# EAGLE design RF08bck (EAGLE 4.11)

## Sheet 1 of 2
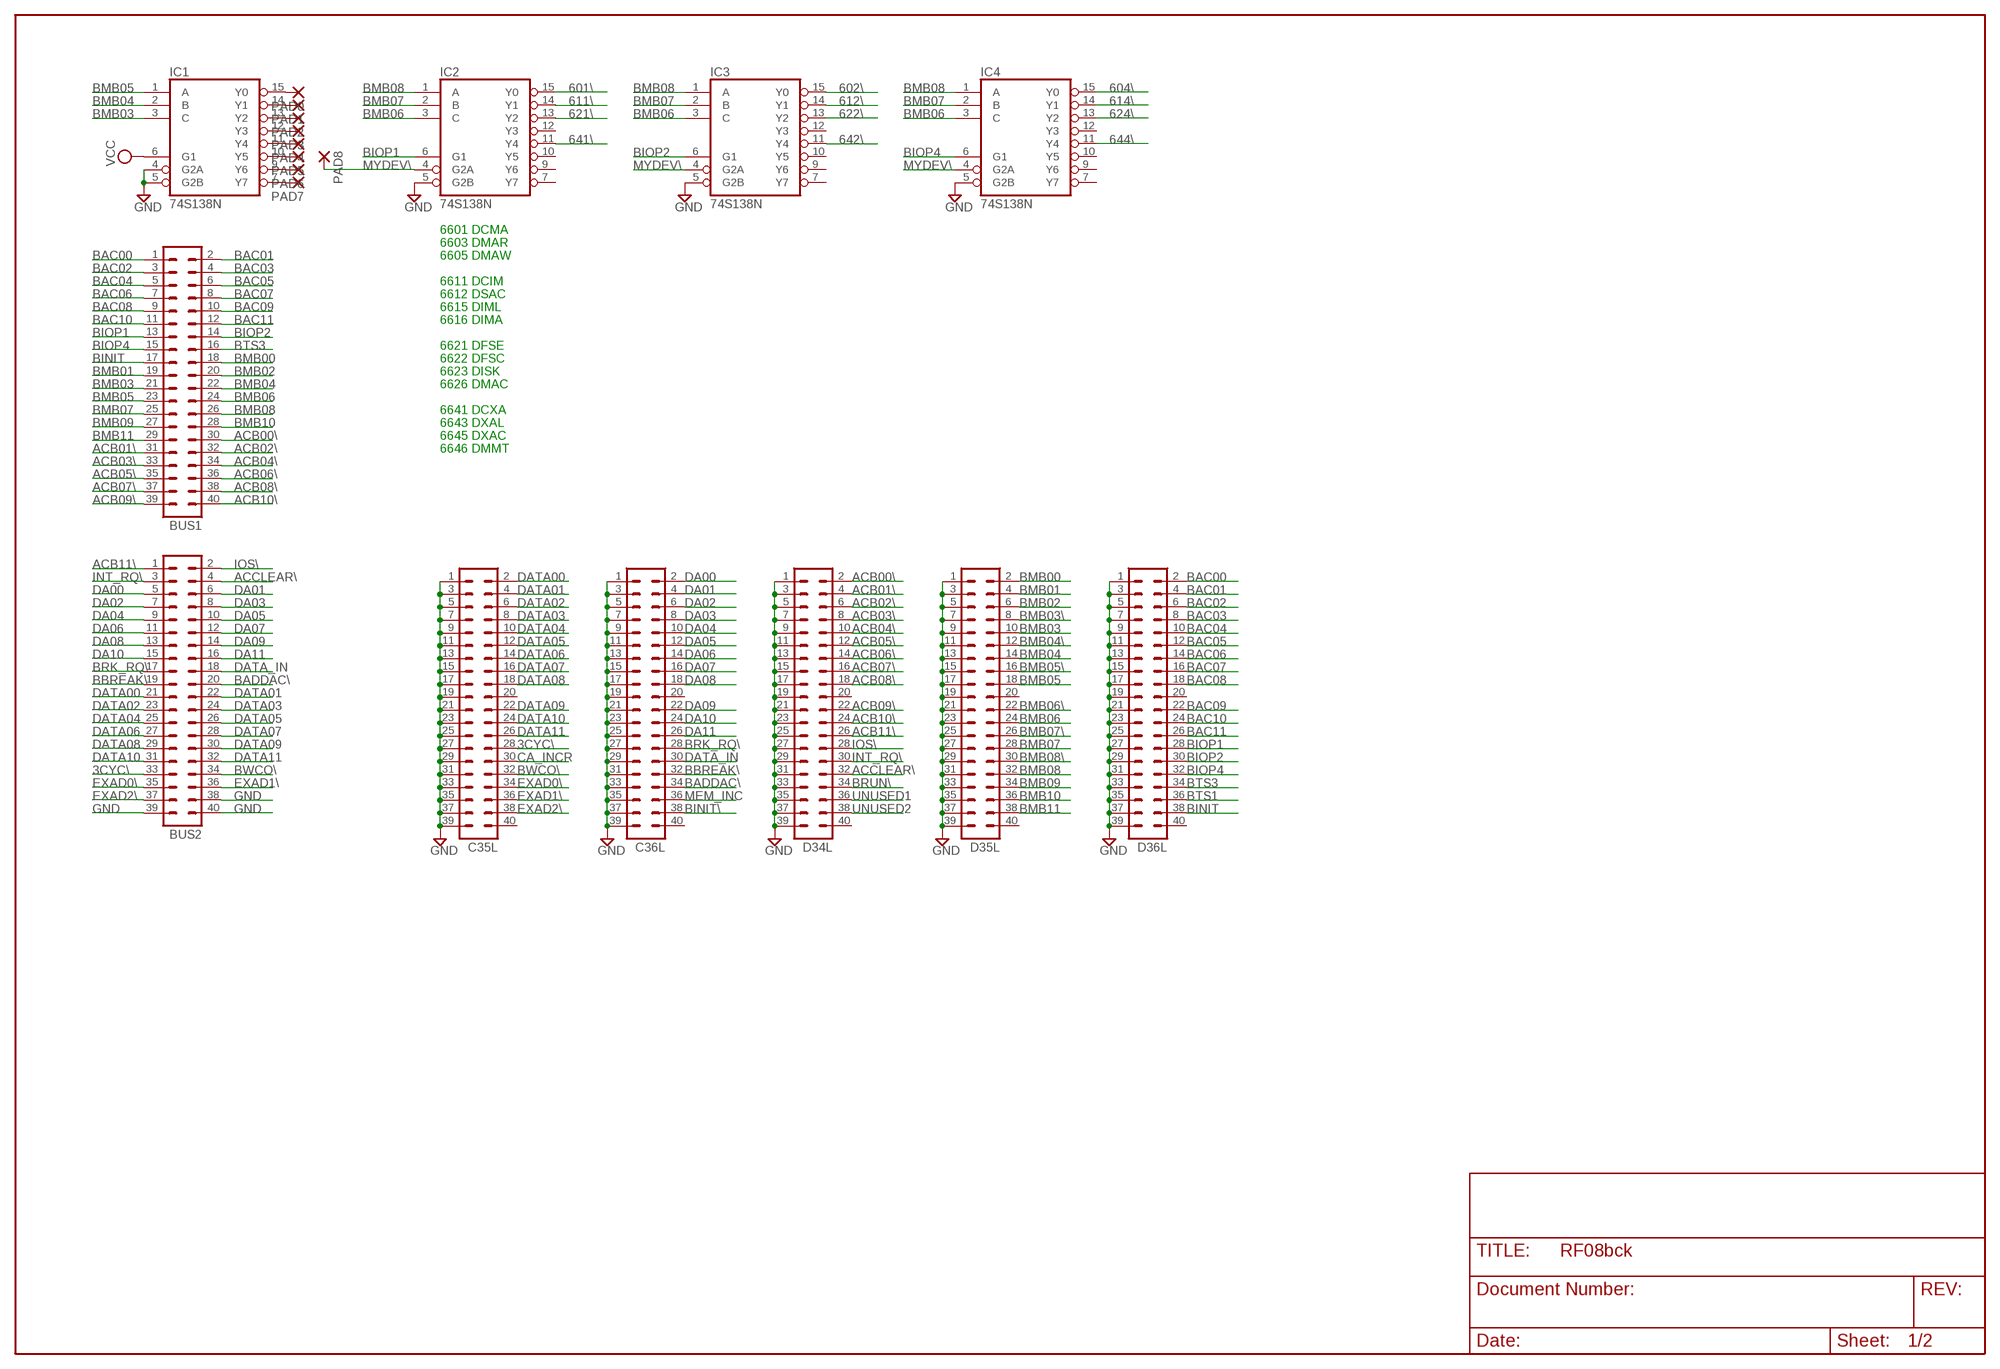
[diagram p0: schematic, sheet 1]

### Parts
BUS1  MA20-2  [MA20-2]
BUS2  MA20-2  [MA20-2]
C35L  MA20-2  [MA20-2]
C36L  MA20-2  [MA20-2]
D34L  MA20-2  [MA20-2]
D35L  MA20-2  [MA20-2]
D36L  MA20-2  [MA20-2]
IC1  74S138N  [DIL16]
IC2  74S138N  [DIL16]
IC3  74S138N  [DIL16]
IC4  74S138N  [DIL16]
PAD0  1,6/0,8  [1,6/0,8]
PAD1  1,6/0,8  [1,6/0,8]
PAD2  1,6/0,8  [1,6/0,8]
PAD3  1,6/0,8  [1,6/0,8]
PAD4  1,6/0,8  [1,6/0,8]
PAD5  1,6/0,8  [1,6/0,8]
PAD6  1,6/0,8  [1,6/0,8]
PAD7  1,6/0,8  [1,6/0,8]
PAD8  1,6/0,8  [1,6/0,8]

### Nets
3CYC\: BUS2.33 C35L.28
601\: IC2.15(Y0) ; also sheet 2
602\: IC3.15(Y0) ; also sheet 2
604\: IC4.15(Y0) ; also sheet 2
611\: IC2.14(Y1)
612\: IC3.14(Y1)
614\: IC4.14(Y1)
621\: IC2.13(Y2)
622\: IC3.13(Y2)
624\: IC4.13(Y2) ; also sheet 2
641\: IC2.11(Y4)
642\: IC3.11(Y4)
644\: IC4.11(Y4)
ACB00\: BUS1.30 D34L.2 ; also sheet 2
ACB01\: BUS1.31 D34L.4 ; also sheet 2
ACB02\: BUS1.32 D34L.6 ; also sheet 2
ACB03\: BUS1.33 D34L.8 ; also sheet 2
ACB04\: BUS1.34 D34L.10 ; also sheet 2
ACB05\: BUS1.35 D34L.12 ; also sheet 2
ACB06\: BUS1.36 D34L.14 ; also sheet 2
ACB07\: BUS1.37 D34L.16 ; also sheet 2
ACB08\: BUS1.38 D34L.18 ; also sheet 2
ACB09\: BUS1.39 D34L.22 ; also sheet 2
ACB10\: BUS1.40 D34L.24 ; also sheet 2
ACB11\: BUS2.1 D34L.26 ; also sheet 2
ACCLEAR\: BUS2.4 D34L.32
BAC00: BUS1.1 D36L.2 ; also sheet 2
BAC01: BUS1.2 D36L.4 ; also sheet 2
BAC02: BUS1.3 D36L.6 ; also sheet 2
BAC03: BUS1.4 D36L.8 ; also sheet 2
BAC04: BUS1.5 D36L.10 ; also sheet 2
BAC05: BUS1.6 D36L.12 ; also sheet 2
BAC06: BUS1.7 D36L.14 ; also sheet 2
BAC07: BUS1.8 D36L.16 ; also sheet 2
BAC08: BUS1.9 D36L.18 ; also sheet 2
BAC09: BUS1.10 D36L.22 ; also sheet 2
BAC10: BUS1.11 D36L.24 ; also sheet 2
BAC11: BUS1.12 D36L.26 ; also sheet 2
BADDAC\: BUS2.20 C36L.34
BBREAK\: BUS2.19 C36L.32
BINIT: BUS1.17 D36L.38
BINIT\: C36L.38
BIOP1: BUS1.13 D36L.28 IC2.6(G1)
BIOP2: BUS1.14 D36L.30 IC3.6(G1)
BIOP4: BUS1.15 D36L.32 IC4.6(G1)
BMB00: BUS1.18 D35L.2
BMB01: BUS1.19 D35L.4
BMB02: BUS1.20 D35L.6
BMB03: BUS1.21 D35L.10 IC1.3(C)
BMB03\: D35L.8
BMB04: BUS1.22 D35L.14 IC1.2(B)
BMB04\: D35L.12
BMB05: BUS1.23 D35L.18 IC1.1(A)
BMB05\: D35L.16
BMB06: BUS1.24 D35L.24 IC2.3(C) IC3.3(C) IC4.3(C)
BMB06\: D35L.22
BMB07: BUS1.25 D35L.28 IC2.2(B) IC3.2(B) IC4.2(B)
BMB07\: D35L.26
BMB08: BUS1.26 D35L.32 IC2.1(A) IC3.1(A) IC4.1(A)
BMB08\: D35L.30
BMB09: BUS1.27 D35L.34
BMB10: BUS1.28 D35L.36
BMB11: BUS1.29 D35L.38
BRK_RQ\: BUS2.17 C36L.28
BRUN\: D34L.34
BTS1: D36L.36
BTS3: BUS1.16 D36L.34
BWCO\: BUS2.34 C35L.32
CA_INCR: C35L.30
DA00: BUS2.5 C36L.2
DA01: BUS2.6 C36L.4
DA02: BUS2.7 C36L.6
DA03: BUS2.8 C36L.8
DA04: BUS2.9 C36L.10
DA05: BUS2.10 C36L.12
DA06: BUS2.11 C36L.14
DA07: BUS2.12 C36L.16
DA08: BUS2.13 C36L.18
DA09: BUS2.14 C36L.22
DA10: BUS2.15 C36L.24
DA11: BUS2.16 C36L.26
DATA00: BUS2.21 C35L.2
DATA01: BUS2.22 C35L.4
DATA02: BUS2.23 C35L.6
DATA03: BUS2.24 C35L.8
DATA04: BUS2.25 C35L.10
DATA05: BUS2.26 C35L.12
DATA06: BUS2.27 C35L.14
DATA07: BUS2.28 C35L.16
DATA08: BUS2.29 C35L.18
DATA09: BUS2.30 C35L.22
DATA10: BUS2.31 C35L.24
DATA11: BUS2.32 C35L.26
DATA_IN: BUS2.18 C36L.30
EXAD0\: BUS2.35 C35L.34
EXAD1\: BUS2.36 C35L.36
EXAD2\: BUS2.37 C35L.38
GND: BUS2.38 BUS2.39 BUS2.40 C35L.1 C35L.3 C35L.5 C35L.7 C35L.9 C35L.11 C35L.13 C35L.15 C35L.17 C35L.19 C35L.21 C35L.23 C35L.25 C35L.27 C35L.29 C35L.31 C35L.33 C35L.35 C35L.37 C35L.39 C36L.1 C36L.3 C36L.5 C36L.7 C36L.9 C36L.11 C36L.13 C36L.15 C36L.17 C36L.19 C36L.21 C36L.23 C36L.25 C36L.27 C36L.29 C36L.31 C36L.33 C36L.35 C36L.37 C36L.39 D34L.1 D34L.3 D34L.5 D34L.7 D34L.9 D34L.11 D34L.13 D34L.15 D34L.17 D34L.19 D34L.21 D34L.23 D34L.25 D34L.27 D34L.29 D34L.31 D34L.33 D34L.35 D34L.37 D34L.39 D35L.1 D35L.3 D35L.5 D35L.7 D35L.9 D35L.11 D35L.13 D35L.15 D35L.17 D35L.19 D35L.21 D35L.23 D35L.25 D35L.27 D35L.29 D35L.31 D35L.33 D35L.35 D35L.37 D35L.39 D36L.1 D36L.3 D36L.5 D36L.7 D36L.9 D36L.11 D36L.13 D36L.15 D36L.17 D36L.19 D36L.21 D36L.23 D36L.25 D36L.27 D36L.29 D36L.31 D36L.33 D36L.35 D36L.37 D36L.39 IC1.4(G2A) IC1.5(G2B) IC2.5(G2B) IC3.5(G2B) IC4.5(G2B) ; also sheet 2
INT_RQ\: BUS2.3 D34L.30
IOS\: BUS2.2 D34L.28
MEM_INC: C36L.36
MYDEV\: IC2.4(G2A) IC3.4(G2A) IC4.4(G2A) PAD8.1(P)
N$1: IC1.9(Y6) PAD6.1(P)
N$5: IC1.15(Y0) PAD0.1(P)
N$6: IC1.14(Y1) PAD1.1(P)
N$7: IC1.13(Y2) PAD2.1(P)
N$8: IC1.12(Y3) PAD3.1(P)
N$9: IC1.11(Y4) PAD4.1(P)
N$10: IC1.10(Y5) PAD5.1(P)
N$11: IC1.7(Y7) PAD7.1(P)
UNUSED1: D34L.36
UNUSED2: D34L.38
VCC: IC1.6(G1)
Unconnected: C35L.20 C35L.40 C36L.20 C36L.40 D34L.20 D34L.40 D35L.20 D35L.40 D36L.20 D36L.40 IC2.7(Y7) IC2.9(Y6) IC2.10(Y5) IC2.12(Y3) IC3.7(Y7) IC3.9(Y6) IC3.10(Y5) IC3.12(Y3) IC4.7(Y7) IC4.9(Y6) IC4.10(Y5) IC4.12(Y3)

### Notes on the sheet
- 6601 DCMA
- 6603 DMAR
- 6605 DMAW
- 6611 DCIM
- 6612 DSAC
- 6615 DIML
- 6616 DIMA
- 6621 DFSE
- 6622 DFSC
- 6623 DISK
- 6626 DMAC
- 6641 DCXA
- 6643 DXAL
- 6645 DXAC
- 6646 DMMT

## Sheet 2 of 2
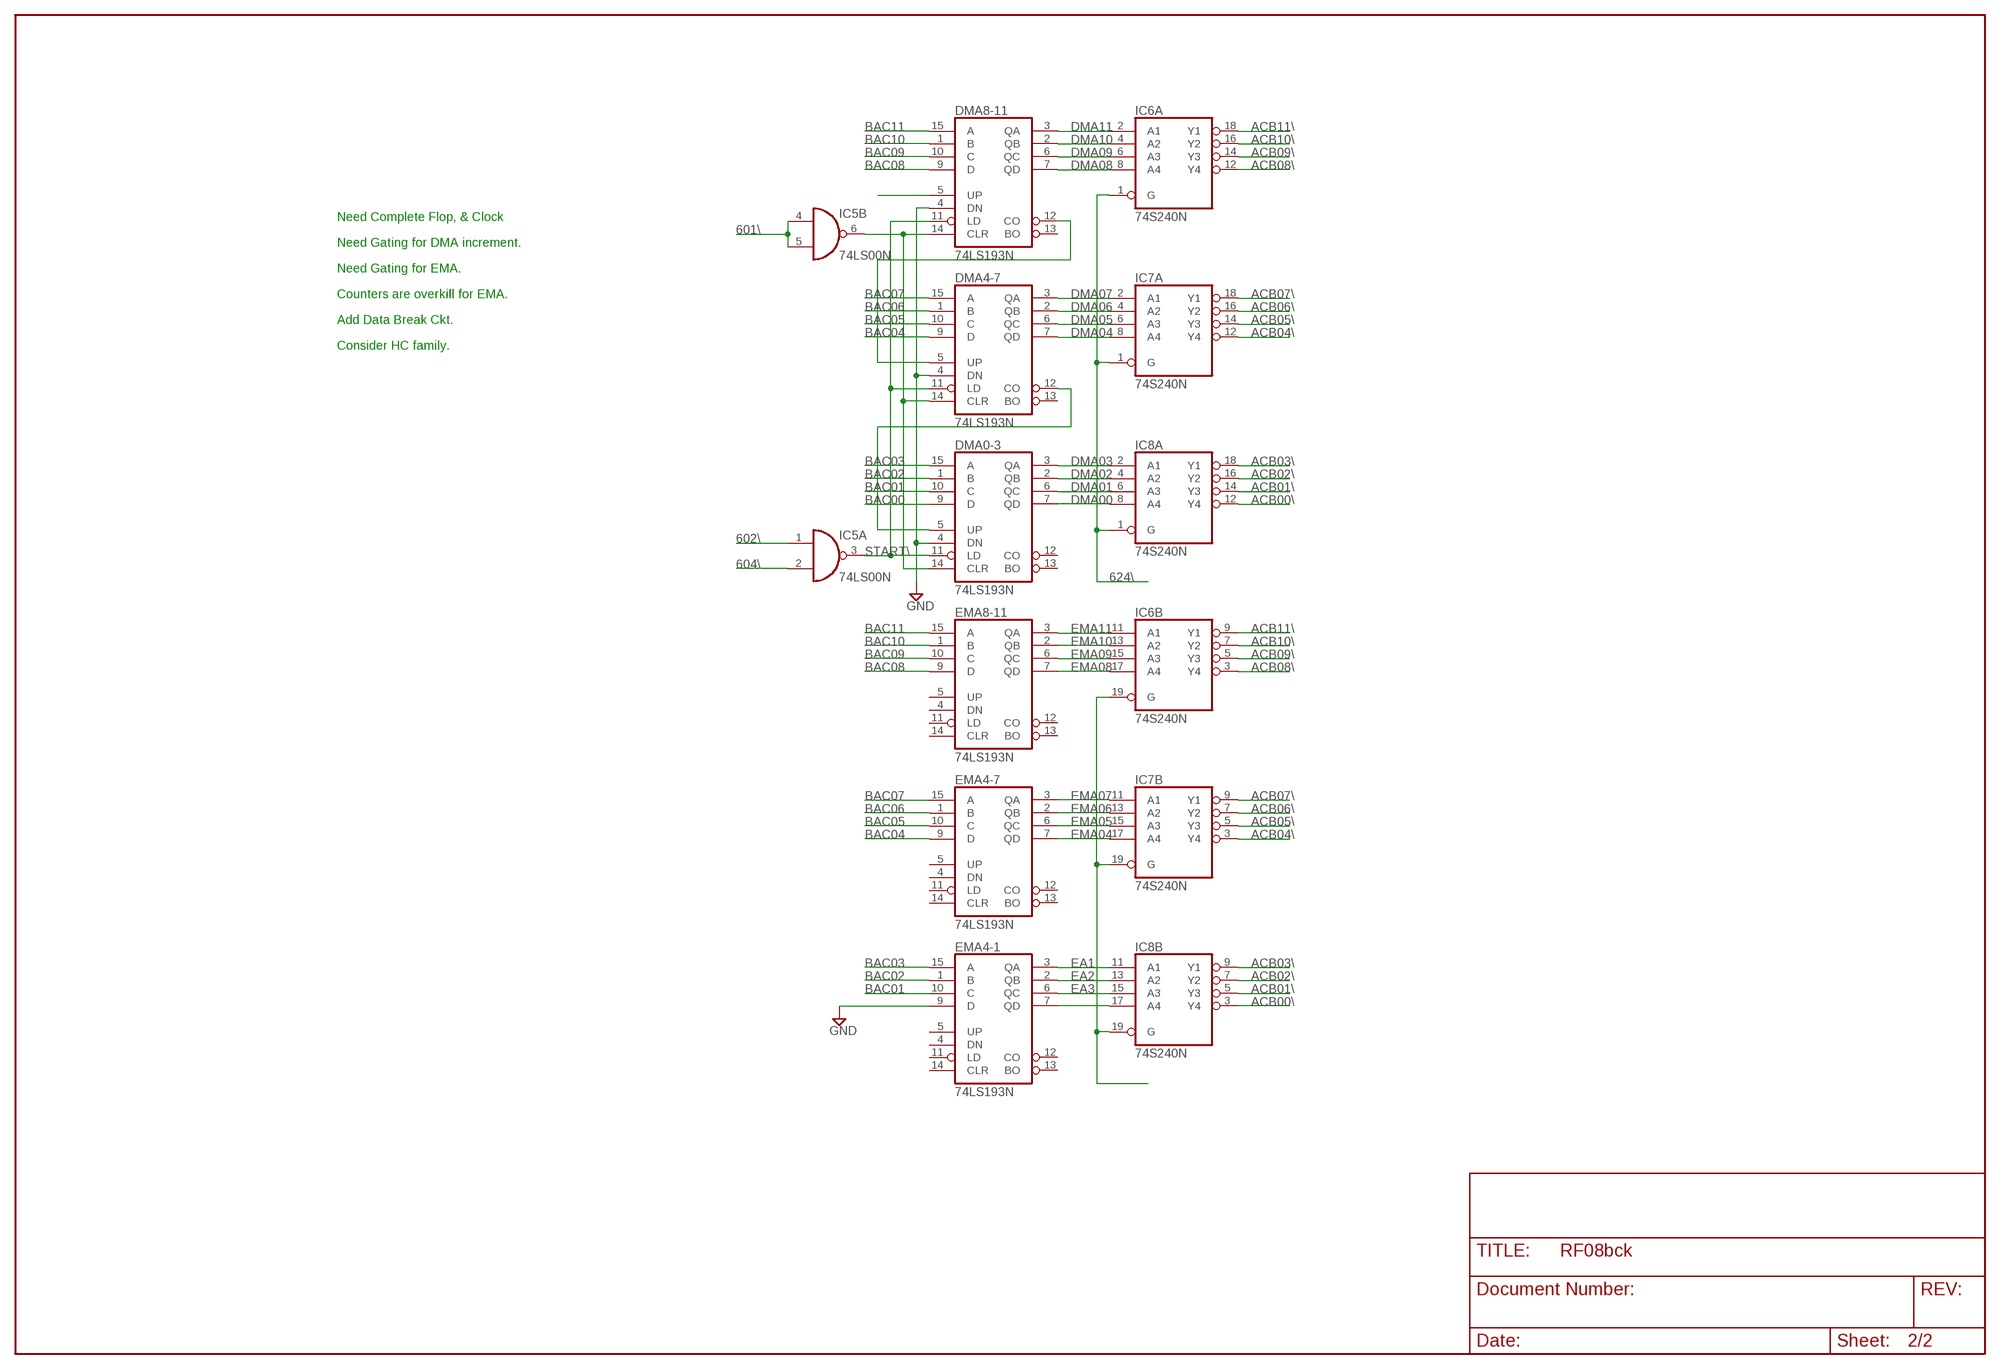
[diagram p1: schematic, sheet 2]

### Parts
DMA0-3  74LS193N  74LS192N  [DIL16]
DMA4-7  74LS193N  74LS192N  [DIL16]
DMA8-11  74LS193N  74LS192N  [DIL16]
EMA4-1  74LS193N  74LS192N  [DIL16]
EMA4-7  74LS193N  74LS192N  [DIL16]
EMA8-11  74LS193N  74LS192N  [DIL16]
IC5  74LS00N  [DIL14]
IC6  74S240N  [DIL20]
IC7  74S240N  [DIL20]
IC8  74S240N  [DIL20]

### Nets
601\: IC5.4(B:I0) IC5.5(B:I1) ; also sheet 1
602\: IC5.1(A:I0) ; also sheet 1
604\: IC5.2(A:I1) ; also sheet 1
624\: IC6.1(A:G) IC7.1(A:G) IC8.1(A:G) ; also sheet 1
ACB00\: IC8.3(B:Y4) IC8.12(A:Y4) ; also sheet 1
ACB01\: IC8.5(B:Y3) IC8.14(A:Y3) ; also sheet 1
ACB02\: IC8.7(B:Y2) IC8.16(A:Y2) ; also sheet 1
ACB03\: IC8.9(B:Y1) IC8.18(A:Y1) ; also sheet 1
ACB04\: IC7.3(B:Y4) IC7.12(A:Y4) ; also sheet 1
ACB05\: IC7.5(B:Y3) IC7.14(A:Y3) ; also sheet 1
ACB06\: IC7.7(B:Y2) IC7.16(A:Y2) ; also sheet 1
ACB07\: IC7.9(B:Y1) IC7.18(A:Y1) ; also sheet 1
ACB08\: IC6.3(B:Y4) IC6.12(A:Y4) ; also sheet 1
ACB09\: IC6.5(B:Y3) IC6.14(A:Y3) ; also sheet 1
ACB10\: IC6.7(B:Y2) IC6.16(A:Y2) ; also sheet 1
ACB11\: IC6.9(B:Y1) IC6.18(A:Y1) ; also sheet 1
BAC00: DMA0-3.9(D) ; also sheet 1
BAC01: DMA0-3.10(C) EMA4-1.10(C) ; also sheet 1
BAC02: DMA0-3.1(B) EMA4-1.1(B) ; also sheet 1
BAC03: DMA0-3.15(A) EMA4-1.15(A) ; also sheet 1
BAC04: DMA4-7.9(D) EMA4-7.9(D) ; also sheet 1
BAC05: DMA4-7.10(C) EMA4-7.10(C) ; also sheet 1
BAC06: DMA4-7.1(B) EMA4-7.1(B) ; also sheet 1
BAC07: DMA4-7.15(A) EMA4-7.15(A) ; also sheet 1
BAC08: DMA8-11.9(D) EMA8-11.9(D) ; also sheet 1
BAC09: DMA8-11.10(C) EMA8-11.10(C) ; also sheet 1
BAC10: DMA8-11.1(B) EMA8-11.1(B) ; also sheet 1
BAC11: DMA8-11.15(A) EMA8-11.15(A) ; also sheet 1
DMA00: DMA0-3.7(QD) IC8.8(A:A4)
DMA01: DMA0-3.6(QC) IC8.6(A:A3)
DMA02: DMA0-3.2(QB) IC8.4(A:A2)
DMA03: DMA0-3.3(QA) IC8.2(A:A1)
DMA04: DMA4-7.7(QD) IC7.8(A:A4)
DMA05: DMA4-7.6(QC) IC7.6(A:A3)
DMA06: DMA4-7.2(QB) IC7.4(A:A2)
DMA07: DMA4-7.3(QA) IC7.2(A:A1)
DMA08: DMA8-11.7(QD) IC6.8(A:A4)
DMA09: DMA8-11.6(QC) IC6.6(A:A3)
DMA10: DMA8-11.2(QB) IC6.4(A:A2)
DMA11: DMA8-11.3(QA) IC6.2(A:A1)
EA1: EMA4-1.3(QA) IC8.11(B:A1)
EA2: EMA4-1.2(QB) IC8.13(B:A2)
EA3: EMA4-1.6(QC) IC8.15(B:A3)
EMA04: EMA4-7.7(QD) IC7.17(B:A4)
EMA05: EMA4-7.6(QC) IC7.15(B:A3)
EMA06: EMA4-7.2(QB) IC7.13(B:A2)
EMA07: EMA4-7.3(QA) IC7.11(B:A1)
EMA08: EMA8-11.7(QD) IC6.17(B:A4)
EMA09: EMA8-11.6(QC) IC6.15(B:A3)
EMA10: EMA8-11.2(QB) IC6.13(B:A2)
EMA11: EMA8-11.3(QA) IC6.11(B:A1)
GND: DMA0-3.4(DN) DMA4-7.4(DN) DMA8-11.4(DN) EMA4-1.9(D) ; also sheet 1
N$3: DMA0-3.5(UP) DMA4-7.12(CO)
N$4: DMA8-11.5(UP)
N$12: EMA4-1.7(QD) IC8.17(B:A4)
N$13: DMA4-7.5(UP) DMA8-11.12(CO)
N$16: IC6.19(B:G) IC7.19(B:G) IC8.19(B:G)
N$22: DMA0-3.14(CLR) DMA4-7.14(CLR) DMA8-11.14(CLR) IC5.6(B:O)
START\: DMA0-3.11(LD) DMA4-7.11(LD) DMA8-11.11(LD) IC5.3(A:O)
Unconnected: DMA0-3.12(CO) DMA0-3.13(BO) DMA4-7.13(BO) DMA8-11.13(BO) EMA4-1.4(DN) EMA4-1.5(UP) EMA4-1.11(LD) EMA4-1.12(CO) EMA4-1.13(BO) EMA4-1.14(CLR) EMA4-7.4(DN) EMA4-7.5(UP) EMA4-7.11(LD) EMA4-7.12(CO) EMA4-7.13(BO) EMA4-7.14(CLR) EMA8-11.4(DN) EMA8-11.5(UP) EMA8-11.11(LD) EMA8-11.12(CO) EMA8-11.13(BO) EMA8-11.14(CLR) IC5.8(C:O) IC5.9(C:I0) IC5.10(C:I1) IC5.11(D:O) IC5.12(D:I0) IC5.13(D:I1)

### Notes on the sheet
- Need Complete Flop, & Clock
- Need Gating for DMA increment.
- Need Gating for EMA.
- Counters are overkill for EMA.
- Add Data Break Ckt.
- Consider HC family.

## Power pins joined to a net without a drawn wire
GND: DMA0-3.8(GND) DMA4-7.8(GND) DMA8-11.8(GND) EMA4-1.8(GND) EMA4-7.8(GND) EMA8-11.8(GND) IC1.8(GND) IC2.8(GND) IC3.8(GND) IC4.8(GND) IC5.7(P:GND) IC6.10(P:GND) IC7.10(P:GND) IC8.10(P:GND)
VCC: DMA0-3.16(VCC) DMA4-7.16(VCC) DMA8-11.16(VCC) EMA4-1.16(VCC) EMA4-7.16(VCC) EMA8-11.16(VCC) IC1.16(VCC) IC2.16(VCC) IC3.16(VCC) IC4.16(VCC) IC5.14(P:VCC) IC6.20(P:VCC) IC7.20(P:VCC) IC8.20(P:VCC)

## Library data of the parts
BUS1 BUS2 C35L C36L D34L D35L D36L = con-lstb:MA20-2: PIN HEADER
DMA0-3 DMA4-7 DMA8-11 EMA4-1 EMA4-7 EMA8-11 = 74xx-us:74*192: Synchronous 4-bit UP/DOWN COUNTER
IC1-IC4 = 74xx-us:74*138: 3-line to 8-line DECODER/DEMULTIPLEXER
IC5 = 74xx-eu:74*00: Quad 2-input NAND gate
IC6-IC8 = 74xx-us:74*240: Octal BUFFER and LINE DRIVER, 3-state
PAD0 PAD1-PAD8 = wirepad:1,6/0,8: THROUGH-HOLE PAD

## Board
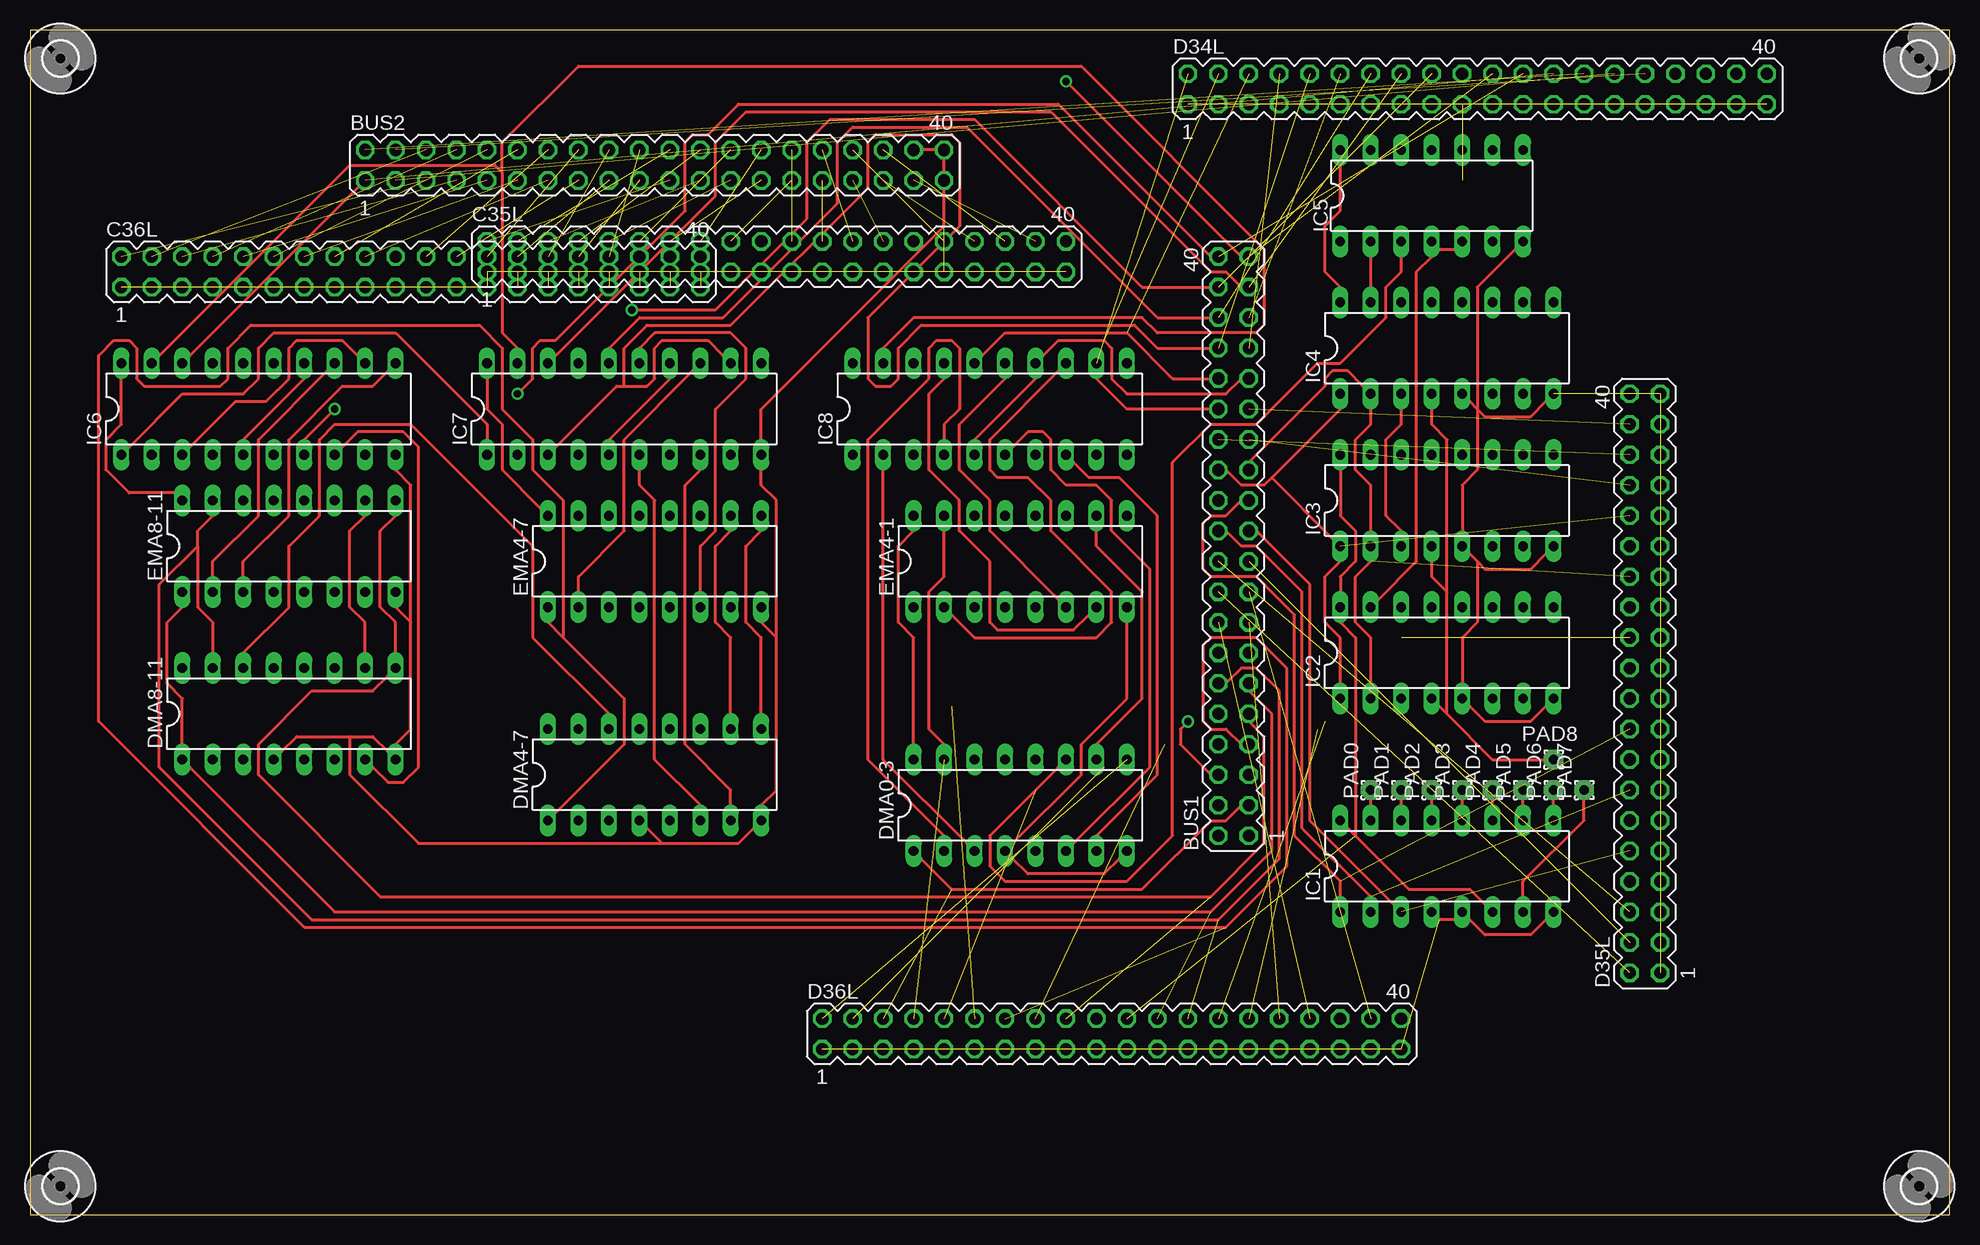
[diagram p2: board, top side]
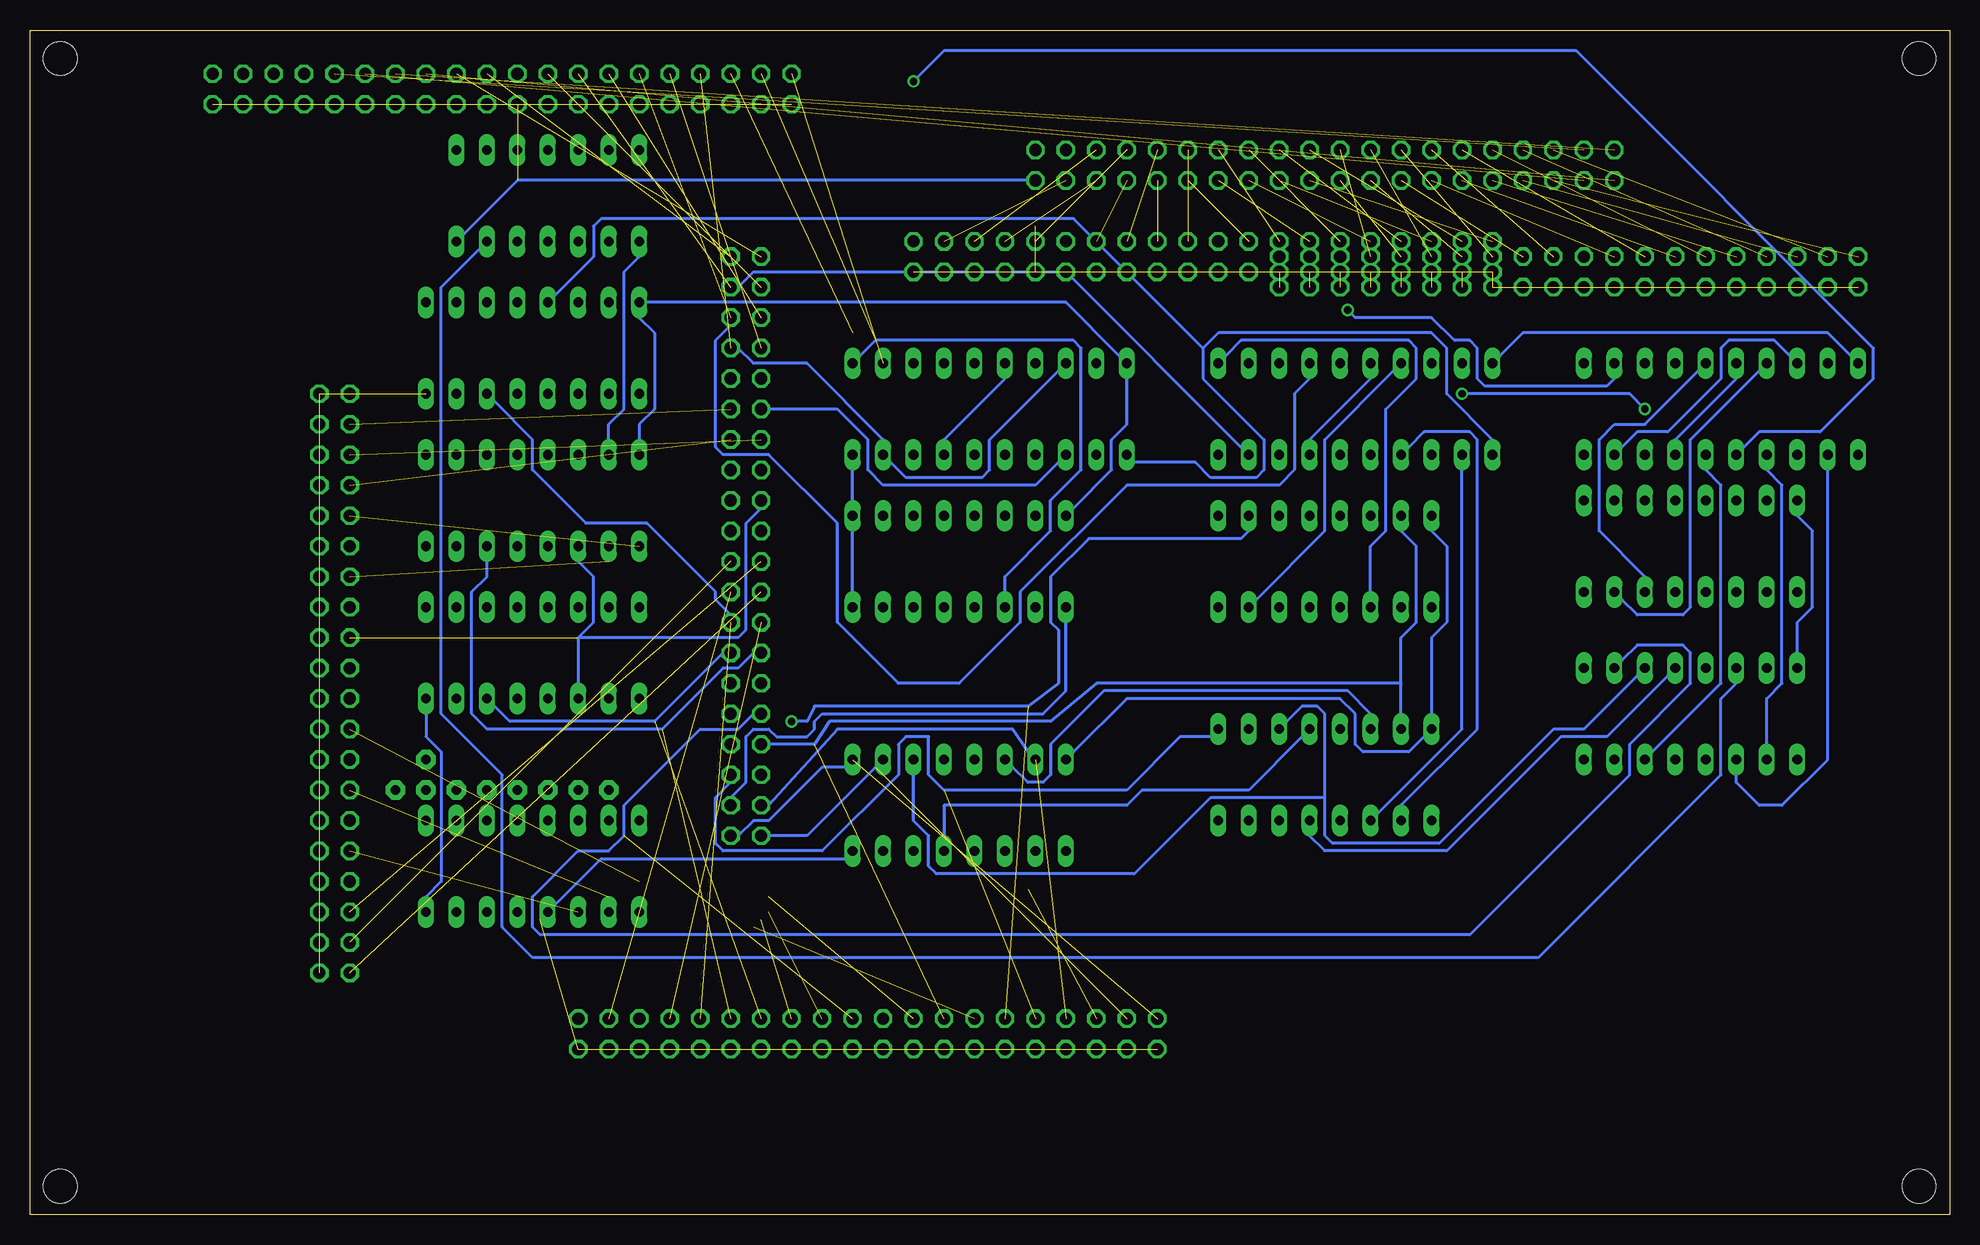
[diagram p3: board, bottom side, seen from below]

Size 160 x 98.73 mm. Coordinates in mm from the lower left corner, seen from the top.
Outline: 0,0 160,0 160,98.73 0,98.73 0,0
Copper layers (1*16): Top 0.035mm / dielectric 1.5mm / Bottom 0.035mm
Design rules "default": minimum track width 10mil, minimum drill 24mil, track to track 8mil, track to pad 8mil, pad to pad 8mil, via to via 8mil, smd to smd 8mil, copper to edge 40mil, drill to drill 8mil, minimum pad ring 10mil, minimum via ring 8mil, stop-mask expansion 4mil, vias tented up to drill 0mil, thermal gap 10mil

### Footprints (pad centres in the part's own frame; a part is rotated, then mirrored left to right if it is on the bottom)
MA20-2 = drill 1.016 octagon: 1 -24.13,-1.27; 2 -24.13,1.27; 3 -21.59,-1.27; 4 -21.59,1.27; 5 -19.05,-1.27; 6 -19.05,1.27; 7 -16.51,-1.27; 8 -16.51,1.27; 9 -13.97,-1.27; 10 -13.97,1.27; 11 -11.43,-1.27; 12 -11.43,1.27; 13 -8.89,-1.27; 14 -8.89,1.27; 15 -6.35,-1.27; 16 -6.35,1.27; 17 -3.81,-1.27; 18 -3.81,1.27; 19 -1.27,-1.27; 20 -1.27,1.27; 21 1.27,-1.27; 22 1.27,1.27; 23 3.81,-1.27; 24 3.81,1.27; 25 6.35,-1.27; 26 6.35,1.27; 27 8.89,-1.27; 28 8.89,1.27; 29 11.43,-1.27; 30 11.43,1.27; 31 13.97,-1.27; 32 13.97,1.27; 33 16.51,-1.27; 34 16.51,1.27; 35 19.05,-1.27; 36 19.05,1.27; 37 21.59,-1.27; 38 21.59,1.27; 39 24.13,-1.27; 40 24.13,1.27
DIL16 = drill 0.813 long: 1 -8.89,-3.81; 2 -6.35,-3.81; 3 -3.81,-3.81; 4 -1.27,-3.81; 5 1.27,-3.81; 6 3.81,-3.81; 7 6.35,-3.81; 8 8.89,-3.81; 9 8.89,3.81; 10 6.35,3.81; 11 3.81,3.81; 12 1.27,3.81; 13 -1.27,3.81; 14 -3.81,3.81; 15 -6.35,3.81; 16 -8.89,3.81
DIL14 = drill 0.813 long: 1 -7.62,-3.81; 2 -5.08,-3.81; 3 -2.54,-3.81; 4 0,-3.81; 5 2.54,-3.81; 6 5.08,-3.81; 7 7.62,-3.81; 8 7.62,3.81; 9 5.08,3.81; 10 2.54,3.81; 11 0,3.81; 12 -2.54,3.81; 13 -5.08,3.81; 14 -7.62,3.81
DIL20 = drill 0.813 long: 1 -11.43,-3.81; 2 -8.89,-3.81; 3 -6.35,-3.81; 4 -3.81,-3.81; 5 -1.27,-3.81; 6 1.27,-3.81; 7 3.81,-3.81; 8 6.35,-3.81; 9 8.89,-3.81; 10 11.43,-3.81; 11 11.43,3.81; 12 8.89,3.81; 13 6.35,3.81; 14 3.81,3.81; 15 1.27,3.81; 16 -1.27,3.81; 17 -3.81,3.81; 18 -6.35,3.81; 19 -8.89,3.81; 20 -11.43,3.81
1,6/0,8 = drill 0.813 pad 1.6 octagon: 1 0,0
2,8 = hole 2.8: 0,0

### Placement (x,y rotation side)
BUS1  100.33,55.72 90 top
BUS2  52.06,87.46 0 top
C35L  62.22,79.84 0 top
C36L  31.75,78.57 0 top
D34L  120.65,93.81 0 top
D35L  134.62,44.29 90 top
D36L  90.17,15.08 0 top
DMA0-3  82.55,34.12 0 top
DMA4-7  52.06,36.66 0 top
DMA8-11  21.59,41.74 0 top
EMA4-1  82.55,54.45 0 top
EMA4-7  52.06,54.45 0 top
EMA8-11  21.59,55.72 0 top
IC1  118.11,29.05 0 top
IC2  118.11,46.83 0 top
IC3  118.11,59.52 0 top
IC4  118.11,72.22 0 top
IC5  116.84,84.92 0 top
IC6  19.05,67.14 0 top
IC7  49.52,67.14 0 top
IC8  80.01,67.14 0 top
PAD0  111.76,35.4 90 top
PAD1  114.3,35.4 90 top
PAD2  116.84,35.4 90 top
PAD3  119.38,35.4 90 top
PAD4  121.92,35.4 90 top
PAD5  124.45,35.4 90 top
PAD6  127,35.4 90 top
PAD7  129.53,35.4 90 top
PAD8  127,37.94 90 top
U$1  [2,8]  157.47,96.35 0 top
U$2  [2,8]  2.54,96.35 0 top
U$3  [2,8]  2.54,2.38 0 top
U$4  [2,8]  157.47,2.38 0 top

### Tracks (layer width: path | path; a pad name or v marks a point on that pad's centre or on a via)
3CYC\  (1 unrouted)
601\
  Top 0.254: IC2.15 112.39,51.27 115.56,54.45 115.56,78.57 116.84,79.84 IC5.4 117.47,80.48 118.74,80.48 IC5.5
602\
  Bottom 0.254: IC3.15 111.76,64.6 111.76,65.88 110.48,67.14 110.48,78.57 109.22,79.84 IC5.1
604\
  Top 0.254: IC4.15 111.76,77.3 111.76,79.84 IC5.2
624\
  Top 0.254: IC6.1 8.25,63.97 12.69,68.41 17.78,68.41 19.05,69.68 19.05,72.22 20.32,73.49 30.48,73.49 38.09,65.88 38.09,64.6 IC7.1
  Bottom 0.254: 62.22,72.22 62.22,69.68 57.14,64.6 57.14,62.06 57.78,61.43 61.59,61.43 62.86,62.7 67.94,62.7 IC8.1 | 62.22,72.22 60.95,73.49 43.17,73.49 41.9,72.22 41.9,68.41 38.09,64.6 IC7.1 | 62.22,72.22 73.02,83.02 112.39,83.02 113.03,82.38 113.03,79.84 116.2,76.67 IC4.13
ACB00\  (1 unrouted)
  Top 0.254: IC8.12 88.9,69.68 91.44,67.14 98.42,67.14 BUS1.30
  Bottom 0.254: IC8.3 74.29,62.7 76.2,60.8 88.9,60.8 90.17,62.06 90.17,64.6 92.7,67.14 98.42,67.14 BUS1.30
ACB01\  (1 unrouted)
  Top 0.254: IC8.5 78.73,64.6 83.81,69.68 IC8.14 84.45,71.59 85.72,72.86 89.53,72.86 90.17,72.22 90.17,69.68 91.44,68.41 99.69,68.41 100.96,69.68 BUS1.31
ACB02\  (1 unrouted)
  Top 0.254: BUS1.32 98.42,69.68 95.25,69.68 91.44,73.49 81.28,73.49 79.37,71.59 IC8.16
  Bottom 0.254: IC8.7 83.81,64.6 78.73,69.68 IC8.16
ACB03\  (1 unrouted)
  Bottom 0.254: IC8.18 74.29,70.32 80.01,64.6 80.01,62.06 80.64,61.43 86.99,61.43 88.26,62.7 IC8.9 88.9,64.6 95.25,70.95 99.69,70.95 100.96,72.22 BUS1.33
ACB04\  (1 unrouted)
  Top 0.254: 49.52,69.05 51.43,69.05 52.06,69.68 52.06,72.22 52.7,72.86 56.51,72.86 57.78,71.59 IC7.12 | 49.52,69.05 48.89,69.05 43.81,63.97 IC7.3 | 49.52,69.05 49.52,72.22 51.43,74.13 58.41,74.13 69.84,85.56 69.84,89.37 70.48,90 76.83,90 77.47,89.37 77.47,82.38 69.84,74.77 69.84,69.68 70.48,69.05 71.75,69.05 72.39,69.68 72.39,72.22 74.29,74.13 92.07,74.13 93.98,72.22 98.42,72.22 BUS1.34
ACB05\  (1 unrouted)
  Top 0.254: IC7.5 48.25,64.6 53.34,69.68 IC7.14
  Bottom 0.254: BUS1.35 101.59,74.13 102.87,72.86 102.87,63.97 102.23,63.34 98.42,63.34 92.7,57.62 92.7,49.37 87.62,44.29 82.55,44.29 77.47,49.37 77.47,51.91 68.58,60.8 55.88,60.8 54.6,62.06 54.6,68.41 53.34,69.68 IC7.14
ACB06\  (1 unrouted)
  Top 0.254: BUS1.36 98.42,74.77 93.98,74.77 78.1,90.64 68.58,90.64 67.31,89.37 67.31,84.29 57.78,74.77 50.79,74.77 48.25,72.22 IC7.16
  Bottom 0.254: IC7.7 53.34,64.6 48.25,69.68 IC7.16
ACB07\  (1 unrouted)
  Top 0.254: IC7.18 43.81,71.59 57.14,84.92 57.14,89.37 59.68,91.91 85.09,91.91 98.42,78.57 99.69,78.57 100.96,77.3 BUS1.37
  Bottom 0.254: IC7.9 59.05,63.97 73.66,78.57 99.69,78.57 100.96,77.3 BUS1.37
ACB08\  (via drill 0.61)  (1 unrouted)
  Top 0.254: IC6.3 13.33,63.97 17.14,67.78 19.68,67.78 21.59,69.68 21.59,72.22 22.22,72.86 26.03,72.86 27.3,71.59 IC6.12 | v50.16,75.4 57.14,75.4 64.77,83.02 64.77,89.37 66.67,91.27 78.73,91.27 92.7,77.3 98.42,77.3 BUS1.38
  Bottom 0.254: v50.16,75.4 49.52,74.77 43.17,74.77 41.27,72.86 40,72.86 39.36,72.22 39.36,69.68 38.73,69.05 28.57,69.05 27.94,69.68 IC6.12
ACB09\  (via drill 0.61)  (1 unrouted)
  Top 0.254: IC6.5 17.78,64.6 22.86,69.68 IC6.14 | v86.36,94.45 100.96,79.84 BUS1.39
  Bottom 0.254: v86.36,94.45 83.81,96.99 31.11,96.99 6.34,72.22 6.34,69.68 10.79,65.24 15.87,65.24 17.14,63.97 IC6.5
ACB10\  (via drill 0.61)  (1 unrouted)
  Top 0.254: v40.63,68.41 41.9,69.68 41.9,72.22 42.54,72.86 43.81,72.86 54.6,83.65 54.6,89.37 55.24,90 56.51,90 59.05,92.54 85.72,92.54 98.42,79.84 BUS1.40 | v25.39,67.14 22.86,64.6 IC6.7
  Bottom 0.254: IC6.7 22.86,64.6 17.78,69.68 IC6.16 | v40.63,68.41 26.67,68.41 v25.39,67.14
ACB11\  (1 unrouted)
  Top 0.254: BUS2.1 13.33,71.59 IC6.18
  Bottom 0.254: IC6.9 27.3,63.97 26.03,65.24 23.49,65.24 19.05,69.68 19.05,72.22 18.41,72.86 14.6,72.86 13.33,71.59 IC6.18
ACCLEAR\  (1 unrouted)
BAC00  (1 unrouted)
  Bottom 0.254: DMA0-3.9 92.07,37.3 93.98,37.3 98.42,32.86 99.69,32.86 100.96,31.59 BUS1.1
BAC01  (1 unrouted)
  Top 0.254: EMA4-1.10 88.9,56.98 88.9,55.72 92.7,51.91 92.7,43.02 88.9,39.2 DMA0-3.10
  Bottom 0.254: DMA0-3.10 89.53,37.3 95.25,31.59 98.42,31.59 BUS1.2
BAC02  (1 unrouted)
  Top 0.254: DMA0-3.1 74.29,29.68 76.83,27.14 92.7,27.14 98.42,32.86 99.69,32.86 100.96,34.12 BUS1.3
  Bottom 0.254: EMA4-1.1 73.66,49.37 73.66,43.65 75.56,41.74 93.98,41.74 94.61,41.11 94.61,40.48 95.25,39.84 97.79,39.84 98.42,40.48 99.69,40.48 100.33,39.84 100.33,36.03 101.59,34.76 BUS1.3
BAC03  (1 unrouted)
  Top 0.254: EMA4-1.15 76.2,56.98 76.2,53.18 74.93,51.91 74.93,40.48 76.2,39.2 DMA0-3.15
  Bottom 0.254: DMA0-3.15 76.83,38.57 78.1,40.48 92.7,40.48 98.42,34.12 BUS1.4
BAC04  (1 unrouted)
  Top 0.254: DMA4-7.9 60.95,41.74 60.95,48.09 59.68,49.37 59.68,55.72 60.95,56.98 EMA4-7.9
  Bottom 0.254: BUS1.5 101.59,36.03 102.87,34.76 102.87,30.95 102.23,30.32 93.98,30.32 87.62,36.66 87.62,39.2 86.99,39.84 85.09,39.84 85.09,36.66 83.81,35.4 68.58,35.4 64.13,39.84 61.59,39.84 DMA4-7.9
BAC05  (via drill 0.61)  (1 unrouted)
  Top 0.254: DMA4-7.10 58.41,41.74 58.41,48.09 57.14,49.37 57.14,55.72 58.41,56.98 EMA4-7.10 | v96.52,41.11 95.88,40.48 95.88,39.2 98.42,36.66 BUS1.6
  Bottom 0.254: v96.52,41.11 95.25,41.11 94.61,42.38 76.83,42.38 74.29,44.29 74.29,48.73 74.93,49.37 74.93,53.18 71.75,56.35 59.05,56.35 58.41,56.98 EMA4-7.10
BAC06  (1 unrouted)
  Top 0.254: 44.45,48.09 43.17,49.37 EMA4-7.1 | 44.45,48.09 49.52,43.02 49.52,39.2 43.81,33.49 DMA4-7.1 | 44.45,48.09 44.45,59.52 41.9,62.06 41.9,64.6 39.36,67.14 39.36,72.22 37.46,74.13 18.41,74.13 16.51,72.22 16.51,69.68 15.87,69.05 9.52,69.05 8.88,69.68 8.88,72.22 8.25,72.86 6.98,72.86 5.71,71.59 5.71,41.11 22.86,23.96 99.69,23.96 104.77,29.05 104.77,45.55 102.23,48.09 98.42,48.09 97.79,47.46 97.79,41.11 98.42,40.48 99.69,40.48 100.96,39.2 BUS1.7
BAC07  (1 unrouted)
  Bottom 0.254: 45.71,44.29 45.71,48.09 44.45,49.37 44.45,55.72 45.71,56.98 EMA4-7.15 | 45.71,44.29 45.71,41.74 DMA4-7.15 | 45.71,44.29 71.12,44.29 74.93,41.11 93.34,41.11 94.61,39.2 98.42,39.2 BUS1.8
BAC08  (1 unrouted)
  Top 0.254: EMA8-11.9 30.48,58.26 29.21,56.98 29.21,50.63 30.48,49.37 30.48,46.83 DMA8-11.9 29.84,44.92 28.57,43.65 23.49,43.65 19.05,39.2 19.05,36.66 29.21,26.51 98.42,26.51 102.87,30.95 102.87,39.84 101.59,41.11 BUS1.9
BAC09  (1 unrouted)
  Top 0.254: DMA8-11.10 27.94,46.83 27.94,49.37 26.67,50.63 26.67,56.98 27.94,58.26 EMA8-11.10
  Bottom 0.254: BUS1.10 99.69,41.74 100.96,40.48 104.14,40.48 110.48,34.12 110.48,31.59 111.76,30.32 114.3,30.32 118.11,26.51 118.11,23.96 117.47,23.33 40,23.33 26.67,36.66 26.67,39.2 21.59,44.29 21.59,46.83 22.22,47.46 26.03,47.46 27.3,46.19 DMA8-11.10
BAC10  (1 unrouted)
  Top 0.254: EMA8-11.1 12.69,50.63 11.42,49.37 11.42,44.29 12.69,43.02 12.69,39.2 DMA8-11.1 13.33,37.3 25.39,25.23 98.42,25.23 103.5,30.32 103.5,41.74 101.59,43.65 BUS1.11
BAC11  (1 unrouted)
  Top 0.254: 13.96,55.72 13.96,56.98 15.23,58.26 EMA8-11.15 | 13.96,55.72 13.96,50.63 15.23,49.37 15.23,46.83 DMA8-11.15 | 13.96,55.72 10.79,52.54 10.79,37.3 23.49,24.6 99.06,24.6 104.14,29.68 104.14,43.65 102.23,45.55 100.96,45.55 99.69,44.29 BUS1.12
BADDAC\  (1 unrouted)
BBREAK\  (1 unrouted)
BINIT  (1 unrouted)
BIOP1  (1 unrouted)
  Bottom 0.254: IC2.6 121.28,42.38 120.01,41.11 107.95,41.11 102.23,46.83 BUS1.13
BIOP2  (1 unrouted)
  Bottom 0.254: IC3.6 121.92,54.45 121.92,53.18 123.19,51.91 123.19,41.74 121.92,40.48 107.31,40.48 102.23,45.55 100.96,45.55 99.69,46.83 BUS1.14
BIOP4  (1 unrouted)
  Bottom 0.254: IC4.6 121.28,67.78 118.11,64.6 118.11,62.06 113.66,57.62 108.58,57.62 102.87,51.91 102.87,51.27 101.59,50 BUS1.15
BMB00  (1 unrouted)
BMB01  (1 unrouted)
BMB02  (1 unrouted)
BMB03  (1 unrouted)
  Top 0.254: IC1.3 113.66,25.87 106.68,32.86 106.68,52.54 102.23,56.98 BUS1.21
BMB04  (1 unrouted)
  Top 0.254: IC1.2 111.76,26.51 106.04,32.22 106.04,51.91 102.23,55.72 100.96,55.72 99.69,56.98 BUS1.22
BMB05  (1 unrouted)
  Top 0.254: IC1.1 109.22,26.51 109.22,27.78 105.41,31.59 105.41,50 102.23,53.18 98.42,53.18 97.79,53.81 97.79,57.62 98.42,58.26 99.69,58.26 100.96,59.52 BUS1.23
BMB06  (1 unrouted)
  Top 0.254: IC4.3 114.3,67.14 114.3,65.88 113.03,64.6 113.03,58.26 114.3,56.98 IC3.3
  Bottom 0.254: 114.3,48.09 114.3,44.29 IC2.3 | 114.3,48.09 113.03,49.37 113.03,53.18 114.3,54.45 IC3.3 | 114.3,48.09 100.96,48.09 100.33,48.73 100.33,57.62 99.06,58.89 BUS1.24
BMB07  (1 unrouted)
  Top 0.254: IC2.2 111.76,44.29 111.76,48.09 110.48,49.37 110.48,53.18 111.76,54.45 IC3.2 111.76,56.98 111.76,60.8 110.48,62.06 110.48,64.6 111.76,65.88 111.76,67.14 IC4.2 111.12,69.05 109.85,70.32 108.58,70.32 107.95,69.68 107.95,69.05 101.59,62.7 BUS1.25
BMB08  (1 unrouted)
  Top 0.254: IC2.1 109.22,44.29 109.22,48.09 107.95,49.37 107.95,53.18 109.22,54.45 IC3.1 108.58,56.35 103.5,61.43 | 103.5,61.43 102.87,60.8 100.96,60.8 99.69,62.06 BUS1.26 | 103.5,61.43 109.22,67.14 IC4.1
BMB09  (1 unrouted)
BMB10  (1 unrouted)
BMB11  (1 unrouted)
BRK_RQ\  (1 unrouted)
BTS3  (1 unrouted)
BWCO\  (1 unrouted)
DA00  (1 unrouted)
DA01  (1 unrouted)
DA02  (1 unrouted)
DA03  (1 unrouted)
DA04  (1 unrouted)
DA05  (1 unrouted)
DA06  (1 unrouted)
DA07  (1 unrouted)
DA08  (1 unrouted)
DA09  (1 unrouted)
DA10  (1 unrouted)
DA11  (1 unrouted)
DATA00  (1 unrouted)
DATA01  (1 unrouted)
DATA02  (1 unrouted)
DATA03  (1 unrouted)
DATA04  (1 unrouted)
DATA05  (1 unrouted)
DATA06  (1 unrouted)
DATA07  (1 unrouted)
DATA08  (1 unrouted)
DATA09  (1 unrouted)
DATA10  (1 unrouted)
DATA11  (1 unrouted)
DATA_IN  (1 unrouted)
DMA00
  Top 0.254: IC8.8 86.99,62.7 88.26,61.43 90.8,61.43 93.98,58.26 93.98,36.66 88.9,31.59 DMA0-3.7
DMA01
  Top 0.254: DMA0-3.6 86.99,30.95 93.34,37.3 93.34,53.81 90.17,56.98 90.17,59.52 88.9,60.8 86.36,60.8 85.09,62.06 85.09,64.6 84.45,65.24 83.18,65.24 81.91,63.97 IC8.6
DMA02
  Top 0.254: DMA0-3.2 76.2,31.59 69.84,37.94 69.84,64.6 74.93,69.68 74.93,72.22 75.56,72.86 76.83,72.86 77.47,72.22 77.47,67.14 76.2,65.88 76.2,64.6 IC8.4
DMA03
  Top 0.254: DMA0-3.3 78.1,30.95 71.12,37.94 71.12,62.06 IC8.2
DMA04
  Top 0.254: DMA4-7.7 58.41,34.12 58.41,35.4 54.6,39.2 54.6,60.8 55.88,62.06 IC7.8
DMA05
  Top 0.254: IC7.6 50.79,62.06 50.79,60.8 52.06,59.52 52.06,37.94 55.88,34.12 DMA4-7.6
DMA06
  Bottom 0.254: DMA4-7.2 45.71,34.12 39.36,40.48 39.36,64.6 40,65.24 43.81,65.24 45.08,63.97 IC7.4
DMA07
  Bottom 0.254: IC7.2 40.63,62.06 40.63,40.48 47.62,33.49 DMA4-7.3
DMA08
  Top 0.254: IC6.8 26.03,63.97 27.3,65.24 31.11,65.24 32.38,63.97 32.38,37.3 31.11,36.03 29.84,36.03 28.57,37.3 DMA8-11.7
DMA09
  Bottom 0.254: DMA8-11.6 24.76,38.57 19.05,44.29 19.05,60.8 20.32,62.06 IC6.6
DMA10
  Bottom 0.254: DMA8-11.2 15.23,39.2 15.23,43.02 13.96,44.29 13.96,60.8 15.23,62.06 IC6.4
DMA11
  Bottom 0.254: IC6.2 10.15,62.06 10.15,37.94 13.96,34.12 15.87,34.12 17.78,36.03 17.78,36.66 DMA8-11.3
EA1
  Bottom 0.254: EMA4-1.3 78.73,51.91 78.73,53.18 74.93,56.98 74.93,59.52 72.39,62.06 72.39,72.22 73.02,72.86 89.53,72.86 90.8,71.59 IC8.11
EA2
  Top 0.254: EMA4-1.2 76.83,50 78.73,48.09 88.9,48.09 90.17,49.37 90.17,51.91 85.09,56.98 85.09,59.52 83.18,61.43 80.64,61.43 80.01,62.06 80.01,64.6 85.72,70.32 IC8.13
EA3
  Top 0.254: EMA4-1.6 85.72,51.27 80.01,56.98 80.01,59.52 77.47,62.06 77.47,65.88 81.28,69.68 IC8.15
EMA04
  Bottom 0.254: IC7.17 46.35,70.32 52.06,64.6 52.06,56.98 57.78,51.27 EMA4-7.7
EMA05
  Top 0.254: EMA4-7.6 55.88,51.91 55.88,55.72 57.14,56.98 57.14,67.14 59.68,69.68 59.68,72.22 58.41,73.49 52.06,73.49 50.79,72.22 IC7.15
EMA06
  Top 0.254: EMA4-7.2 45.71,51.91 45.71,53.18 49.52,56.98 49.52,64.6 55.24,70.32 IC7.13
EMA07
  Bottom 0.254: EMA4-7.3 48.25,51.91 48.25,55.72 46.98,56.98 46.98,67.14 44.45,69.68 44.45,72.22 45.08,72.86 59.05,72.86 60.32,71.59 IC7.11
EMA08
  Bottom 0.254: EMA8-11.7 27.3,51.27 26.03,50 22.22,50 21.59,50.63 21.59,64.6 15.87,70.32 IC6.17
EMA09
  Bottom 0.254: IC6.15 20.95,70.32 25.39,65.88 27.94,65.88 29.21,64.6 29.21,56.98 25.39,53.18 EMA8-11.6
EMA10
  Top 0.254: EMA8-11.2 15.23,53.18 15.23,54.45 19.05,58.26 19.05,64.6 24.76,70.32 IC6.13
EMA11
  Top 0.254: EMA8-11.3 17.78,53.18 17.78,54.45 21.59,58.26 21.59,64.6 26.03,69.05 28.57,69.05 29.84,70.32 IC6.11
EXAD0\  (1 unrouted)
EXAD1\  (1 unrouted)
EXAD2\  (1 unrouted)
GND  (100 unrouted)
  Top 0.254: IC2.8 126.36,42.38 125.09,41.11 121.28,41.11 120.01,42.38 IC2.5 119.38,44.29 119.38,48.09 120.65,49.37 120.65,54.45 | 120.65,54.45 121.28,53.81 125.09,53.81 126.36,55.08 IC3.8 | 120.65,54.45 120.01,55.08 IC3.5 119.38,56.98 119.38,60.8 120.65,62.06 120.65,67.14 | 120.65,67.14 121.28,66.51 125.09,66.51 126.36,67.78 IC4.8 | 120.65,67.14 120.01,67.78 IC4.5 | 120.65,67.14 120.65,77.3 123.82,80.48 IC5.7 | IC1.4 117.47,24.6 118.74,24.6 IC1.5 120.01,24.6 121.28,23.33 125.09,23.33 126.36,24.6 IC1.8 | DMA0-3.8 90.8,29.68 89.53,28.41 83.18,28.41 81.91,29.68 DMA0-3.4 81.91,30.95 87.62,36.66 87.62,39.2 91.44,43.02 91.44,49.37 EMA4-1.8 | 26.67,39.84 28.57,39.84 29.84,38.57 DMA8-11.8 30.48,39.2 31.75,40.48 31.75,49.37 | 26.67,39.84 22.22,39.84 20.95,38.57 DMA8-11.4 | 31.75,49.37 30.48,50.63 EMA8-11.8 | 31.75,49.37 31.75,60.8 30.48,62.06 IC6.10 | BUS2.38 74.29,88.73 75.56,88.73 BUS2.40 76.2,88.1 76.2,86.83 BUS2.39 76.2,85.56 76.2,82.38 60.95,67.14 60.95,64.6 IC7.10 60.95,62.06 60.95,60.8 62.22,59.52 62.22,48.09 | 52.7,30.95 51.43,32.22 DMA4-7.4 | 52.7,30.95 59.05,30.95 60.32,32.22 DMA4-7.8 60.95,34.12 62.22,35.4 62.22,48.09 | 62.22,48.09 60.95,49.37 EMA4-7.8 | 26.67,39.84 26.67,36.66 32.38,30.95 52.7,30.95
  Bottom 0.254: EMA4-1.8 91.44,51.91 91.44,56.98 EMA4-1.9 91.44,59.52 91.44,62.06 IC8.10 | IC1.4 116.2,25.87 112.39,29.68 92.07,29.68 DMA0-3.8 | IC2.8 127,41.74 127,39.84 125.73,38.57 125.73,27.78 127,26.51 IC1.8 | IC5.7 123.82,81.75 119.38,86.19 76.83,86.19 BUS2.39
INT_RQ\  (1 unrouted)
IOS\  (1 unrouted)
MYDEV\
  Top 0.254: 118.11,41.74 121.92,37.94 126.36,37.94 PAD8.1 | 118.11,41.74 117.47,42.38 IC2.4 | 118.11,51.91 116.84,53.18 116.84,54.45 IC3.4 | 118.11,41.74 118.11,51.91 | 118.11,51.91 118.11,64.6 116.84,65.88 116.84,67.14 IC4.4
N$1
  Top 0.254: IC1.9 127,34.12 127,34.76 PAD6.1
N$3
  Bottom 0.254: DMA0-3.5 83.81,31.59 83.81,34.12 68.58,34.12 67.31,35.4 58.41,35.4 53.97,39.84 DMA4-7.12
N$5
  Top 0.254: IC1.15 111.76,34.12 111.76,34.76 PAD0.1
N$6
  Top 0.254: IC1.14 114.3,34.12 114.3,34.76 PAD1.1
N$7
  Top 0.254: IC1.13 116.84,34.12 116.84,34.76 PAD2.1
N$8
  Top 0.254: IC1.12 119.38,34.12 119.38,34.76 PAD3.1
N$9
  Top 0.254: IC1.11 121.92,34.12 121.92,34.76 PAD4.1
N$10
  Top 0.254: IC1.10 124.45,34.12 124.45,34.76 PAD5.1
N$11
  Top 0.254: IC1.7 124.45,26.51 124.45,27.78 129.53,32.86 129.53,34.76 PAD7.1
N$12
  Top 0.254: EMA4-1.7 88.26,50 86.99,48.73 80.64,48.73 80.01,49.37 80.01,54.45 77.47,56.98 77.47,59.52 74.93,62.06 74.93,68.41 76.2,69.68 IC8.17
N$13
  Bottom 0.254: DMA8-11.12 23.49,44.92 28.57,39.84 32.38,39.84 41.9,30.32 52.06,30.32 53.34,31.59 DMA4-7.5
N$16
  Top 0.254: 39.36,86.83 38.73,87.46 26.67,87.46 10.79,71.59 IC6.19 | 39.36,86.83 39.36,73.49 40.63,72.22 IC7.19 | 39.36,86.83 39.36,89.37 45.71,95.72 87.62,95.72 102.87,80.48 102.87,74.13 102.23,73.49 93.98,73.49 92.7,74.77 73.66,74.77 71.12,72.22 IC8.19
N$22
  Top 0.254: DMA8-11.14 17.78,46.83 21.59,50.63 21.59,55.72 24.12,58.26 24.12,64.6 25.39,65.88 31.75,65.88 41.9,55.72 41.9,48.09 48.25,41.74 DMA4-7.14
  Bottom 0.254: DMA0-3.14 78.1,37.3 76.83,36.03 75.56,36.03 74.93,36.66 74.93,39.2 70.48,43.65 50.16,43.65 48.25,41.74 DMA4-7.14 | IC5.6 122.55,80.48 125.73,77.3 125.73,41.74 120.65,36.66 120.65,23.96 118.11,21.43 34.28,21.43 19.05,36.66 19.05,43.02 17.78,44.29 DMA8-11.14
START\
  Top 0.254: IC5.3 114.3,79.84 114.3,78.57 113.03,77.3 113.03,74.77 109.22,70.95 107.31,70.95 102.23,65.88 98.42,65.88 95.25,62.7 95.25,31.59 91.44,27.78 81.28,27.78 80.01,29.05 80.01,31.59 85.72,37.3 DMA0-3.11
  Bottom 0.254: 52.06,34.76 52.06,41.74 52.7,42.38 53.97,42.38 55.24,41.11 DMA4-7.11 | 52.06,34.76 52.06,31.59 51.43,30.95 42.54,30.95 33.02,40.48 30.48,40.48 26.03,44.92 DMA8-11.11 | 52.06,34.76 61.59,34.76 67.94,28.41 84.45,28.41 85.09,29.05 85.09,31.59 86.36,32.86 86.36,36.66 DMA0-3.11
VCC
  Top 0.254: IC6.20 7.62,69.68 7.62,65.88 6.34,64.6 6.34,62.06 8.25,60.16 12.06,60.16 EMA8-11.16 | IC7.20 38.09,69.68 38.09,67.14 39.36,65.88 39.36,62.06 42.54,58.89 EMA4-7.16 | DMA0-3.16 73.66,39.2 73.66,48.09 72.39,49.37 72.39,55.72 73.66,56.98 EMA4-1.16 | IC5.14 109.22,87.46 109.22,83.65 107.95,82.38 107.95,78.57 109.22,77.3 IC4.16 | 110.48,31.59 114.93,27.14 120.01,27.14 121.28,25.87 IC1.6 | 110.48,31.59 109.85,32.22 IC1.16 | 110.48,31.59 110.48,48.09 109.22,49.37 IC2.16 109.22,51.91 109.22,53.18 110.48,54.45 110.48,56.98 109.22,58.26 109.22,62.06 IC3.16
  Bottom 0.254: DMA8-11.16 12.69,46.83 12.69,49.37 11.42,50.63 11.42,56.98 12.69,58.26 EMA8-11.16 | EMA4-7.16 43.17,56.98 41.9,55.72 41.9,49.37 43.17,48.09 43.17,41.74 DMA4-7.16 43.81,39.84 45.08,38.57 48.89,38.57 49.52,39.2 49.52,41.74 50.79,43.02 68.58,43.02 73.02,38.57 DMA0-3.16 | IC6.20 8.25,71.59 10.15,73.49 35.55,73.49 37.46,71.59 IC7.20 | EMA4-1.16 73.02,58.89 69.84,62.06 69.84,64.6 68.58,65.88 68.58,69.68 IC8.20 69.21,71.59 73.66,76.03 108.58,76.03 IC4.16 109.22,74.77 107.95,73.49 107.95,67.14 109.22,65.88 109.22,64.6 IC3.16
